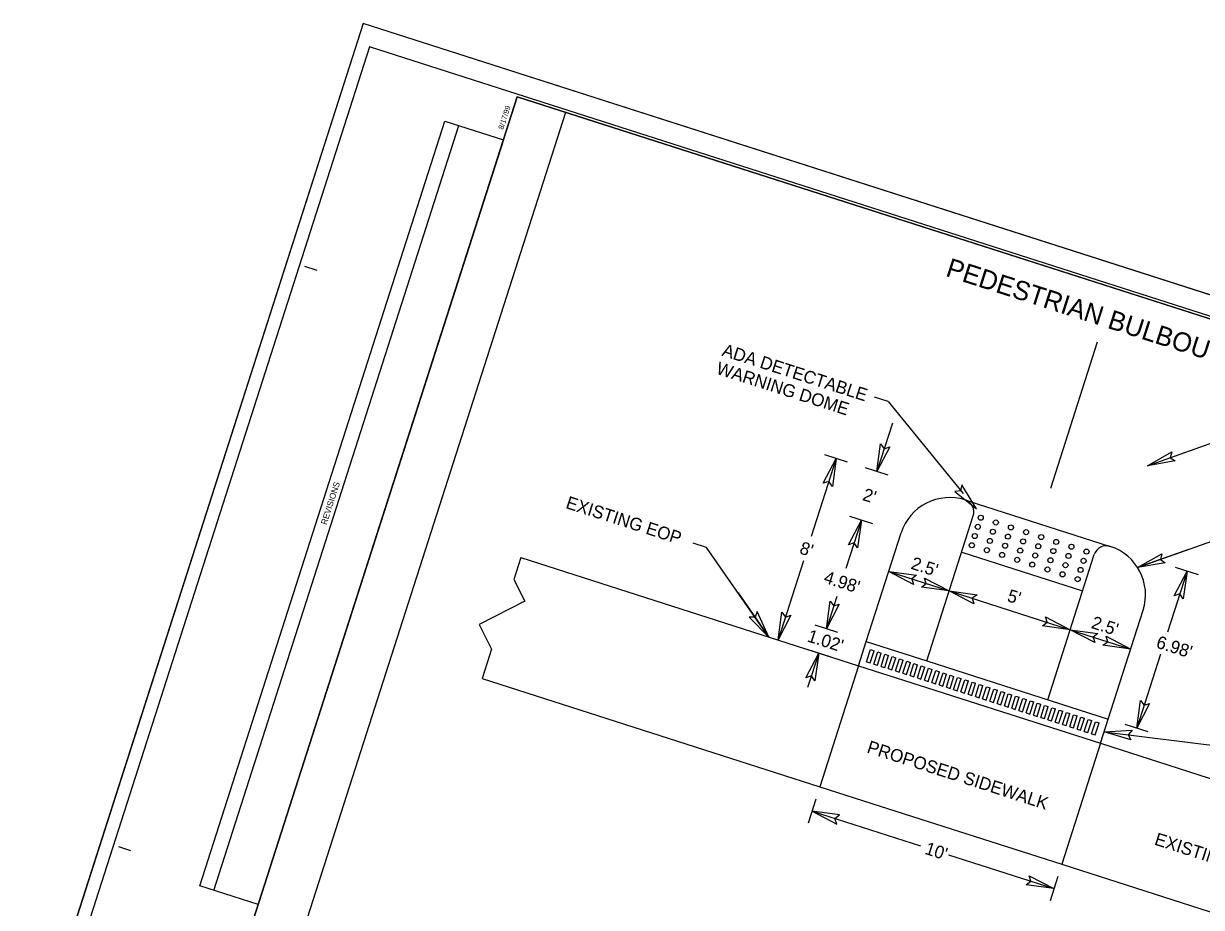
# Model space of a CAD drawing. Extents: x 928111 to 937215, y 684320 to 686530.
# Drawn here: x 933624.35 to 933670.73, y 684716.03 to 684750.83 of the extents above; entities that cross this region are included whole.
import ezdxf

# ---------------------------------------------------------------- set-up
doc = ezdxf.new("R2010")
doc.units = 0
for name, color, linetype in [('Default', 7, 'Continuous'), ('Exist Roads EOP', 7, 'Continuous'), ('Prop Conc 5in Monolithic Keyed In Island', 7, 'Continuous'), ('Prop Conc Curb 8in x 6in', 7, 'Continuous'), ('Prop Dimension', 7, 'Continuous'), ('Prop DSN Text', 7, 'Continuous'), ('Prop Mkg Solid White Crosswalks', 7, 'Continuous'), ('Prop Terminator CELL', 7, 'Continuous'), ('Sheet Block Revision CELL', 7, 'Continuous'), ('Sheet Clip Boundary CELL', 7, 'Continuous'), ('Sheet Cutting Line CELL', 7, 'Continuous'), ('Sheet Layout Plan Border', 7, 'Continuous'), ('Sheet Plan CELL', 7, 'Continuous'), ('Sheet Plan Layout CELL', 7, 'Continuous'), ('Sheet Plot Border Inside CELL', 7, 'Continuous'), ('Sheet Plot Border Outside CELL', 7, 'Continuous')]:
    doc.layers.add(name, color=color, linetype=linetype)

msp = doc.modelspace()

# ---------------------------------------------------------------- linework, layer by layer
at = {"layer": 'Default'}
for p, q in [((933658.389, 684735.948), (933661.338, 684732.328)), ((933670.213, 684730.121), (933668.213, 684729.41)), ((933652.482, 684728.417), (933653.696, 684726.676))]:
    msp.add_line(p, q, dxfattribs=at)
at = {"layer": 'Exist Roads EOP'}
for p, q in [((933643.933, 684729.806), (933643.654, 684728.936)), ((933643.933, 684729.806), (933657.227, 684725.544)), ((933643.654, 684728.936), (933644.089, 684728.092)), ((933644.089, 684728.092), (933642.286, 684727.164)), ((933642.286, 684727.164), (933642.779, 684726.205)), ((933642.779, 684726.205), (933642.407, 684725.044)), ((933642.407, 684725.044), (933655.701, 684720.783)), ((933666.75, 684722.492), (933680.951, 684717.94)), ((933665.223, 684717.731), (933679.425, 684713.179))]:
    msp.add_line(p, q, dxfattribs=at)
at = {"layer": 'Prop Conc 5in Monolithic Keyed In Island'}
for p, q in [((933659.913, 684725.734), (933661.744, 684731.447)), ((933657.532, 684726.497), (933658.906, 684730.782)), ((933664.674, 684724.207), (933666.506, 684729.921)), ((933667.055, 684723.444), (933668.428, 684727.73)), ((933657.227, 684725.544), (933657.532, 684726.497)), ((933657.541, 684725.706), (933657.694, 684726.182)), ((933657.684, 684725.66), (933657.837, 684726.137)), ((933657.694, 684726.182), (933657.837, 684726.137)), ((933657.827, 684725.615), (933657.979, 684726.091)), ((933657.97, 684725.569), (933658.122, 684726.045)), ((933657.979, 684726.091), (933658.122, 684726.045)), ((933658.113, 684725.523), (933658.265, 684725.999)), ((933658.255, 684725.477), (933658.408, 684725.953)), ((933658.265, 684725.999), (933658.408, 684725.953)), ((933658.398, 684725.432), (933658.551, 684725.908)), ((933658.551, 684725.908), (933658.694, 684725.862)), ((933657.227, 684725.544), (933655.701, 684720.783)), ((933657.227, 684725.544), (933659.607, 684724.781)), ((933657.541, 684725.706), (933657.684, 684725.66)), ((933657.827, 684725.615), (933657.97, 684725.569)), ((933658.113, 684725.523), (933658.255, 684725.477)), ((933658.541, 684725.386), (933658.694, 684725.862)), ((933658.684, 684725.34), (933658.836, 684725.816)), ((933658.827, 684725.294), (933658.979, 684725.77)), ((933658.836, 684725.816), (933658.979, 684725.77)), ((933658.97, 684725.248), (933659.122, 684725.724)), ((933659.112, 684725.203), (933659.265, 684725.679)), ((933659.122, 684725.724), (933659.265, 684725.679)), ((933659.255, 684725.157), (933659.408, 684725.633)), ((933659.398, 684725.111), (933659.551, 684725.587)), ((933659.408, 684725.633), (933659.551, 684725.587)), ((933659.541, 684725.065), (933659.694, 684725.541)), ((933659.684, 684725.019), (933659.836, 684725.496)), ((933659.694, 684725.541), (933659.836, 684725.496)), ((933659.827, 684724.974), (933659.979, 684725.45)), ((933659.979, 684725.45), (933660.122, 684725.404)), ((933658.398, 684725.432), (933658.541, 684725.386)), ((933658.684, 684725.34), (933658.827, 684725.294)), ((933658.97, 684725.248), (933659.112, 684725.203)), ((933659.255, 684725.157), (933659.398, 684725.111)), ((933659.541, 684725.065), (933659.684, 684725.019)), ((933659.827, 684724.974), (933659.969, 684724.928)), ((933659.969, 684724.928), (933660.122, 684725.404)), ((933660.112, 684724.882), (933660.265, 684725.358)), ((933660.255, 684724.836), (933660.408, 684725.312)), ((933660.265, 684725.358), (933660.408, 684725.312)), ((933660.398, 684724.79), (933660.551, 684725.267)), ((933660.541, 684724.745), (933660.693, 684725.221)), ((933660.551, 684725.267), (933660.693, 684725.221)), ((933660.684, 684724.699), (933660.836, 684725.175)), ((933660.826, 684724.653), (933660.979, 684725.129)), ((933660.836, 684725.175), (933660.979, 684725.129)), ((933660.969, 684724.607), (933661.122, 684725.083)), ((933661.112, 684724.562), (933661.265, 684725.038)), ((933661.122, 684725.083), (933661.265, 684725.038)), ((933661.255, 684724.516), (933661.408, 684724.992)), ((933661.408, 684724.992), (933661.55, 684724.946)), ((933659.607, 684724.781), (933666.75, 684722.492)), ((933660.112, 684724.882), (933660.255, 684724.836)), ((933660.398, 684724.79), (933660.541, 684724.745)), ((933660.684, 684724.699), (933660.826, 684724.653)), ((933660.969, 684724.607), (933661.112, 684724.562)), ((933661.255, 684724.516), (933661.398, 684724.47)), ((933661.398, 684724.47), (933661.55, 684724.946)), ((933661.541, 684724.424), (933661.693, 684724.9)), ((933661.684, 684724.378), (933661.836, 684724.855)), ((933661.693, 684724.9), (933661.836, 684724.855)), ((933661.826, 684724.333), (933661.979, 684724.809)), ((933661.969, 684724.287), (933662.122, 684724.763)), ((933661.979, 684724.809), (933662.122, 684724.763)), ((933662.112, 684724.241), (933662.265, 684724.717)), ((933662.255, 684724.195), (933662.408, 684724.671)), ((933662.265, 684724.717), (933662.408, 684724.671)), ((933662.398, 684724.149), (933662.55, 684724.626)), ((933662.541, 684724.104), (933662.693, 684724.58)), ((933662.55, 684724.626), (933662.693, 684724.58)), ((933662.683, 684724.058), (933662.836, 684724.534)), ((933662.836, 684724.534), (933662.979, 684724.488)), ((933661.541, 684724.424), (933661.684, 684724.378)), ((933661.826, 684724.333), (933661.969, 684724.287)), ((933662.112, 684724.241), (933662.255, 684724.195)), ((933662.398, 684724.149), (933662.541, 684724.104)), ((933662.683, 684724.058), (933662.826, 684724.012)), ((933662.826, 684724.012), (933662.979, 684724.488)), ((933662.969, 684723.966), (933663.122, 684724.442)), ((933663.112, 684723.921), (933663.265, 684724.397)), ((933663.122, 684724.442), (933663.265, 684724.397)), ((933663.255, 684723.875), (933663.407, 684724.351)), ((933663.398, 684723.829), (933663.55, 684724.305)), ((933663.407, 684724.351), (933663.55, 684724.305)), ((933663.54, 684723.783), (933663.693, 684724.259)), ((933663.683, 684723.737), (933663.836, 684724.214)), ((933663.693, 684724.259), (933663.836, 684724.214)), ((933663.826, 684723.692), (933663.979, 684724.168)), ((933663.969, 684723.646), (933664.122, 684724.122)), ((933663.979, 684724.168), (933664.122, 684724.122)), ((933664.112, 684723.6), (933664.264, 684724.076)), ((933664.264, 684724.076), (933664.407, 684724.03)), ((933662.969, 684723.966), (933663.112, 684723.921)), ((933663.255, 684723.875), (933663.398, 684723.829)), ((933663.54, 684723.783), (933663.683, 684723.737)), ((933663.826, 684723.692), (933663.969, 684723.646)), ((933664.112, 684723.6), (933664.255, 684723.554)), ((933664.255, 684723.554), (933664.407, 684724.03)), ((933664.398, 684723.508), (933664.55, 684723.985)), ((933664.54, 684723.463), (933664.693, 684723.939)), ((933664.55, 684723.985), (933664.693, 684723.939)), ((933664.683, 684723.417), (933664.836, 684723.893)), ((933664.826, 684723.371), (933664.979, 684723.847)), ((933664.836, 684723.893), (933664.979, 684723.847)), ((933664.969, 684723.325), (933665.122, 684723.801)), ((933665.112, 684723.28), (933665.264, 684723.756)), ((933665.122, 684723.801), (933665.264, 684723.756)), ((933665.255, 684723.234), (933665.407, 684723.71)), ((933665.397, 684723.188), (933665.55, 684723.664)), ((933665.407, 684723.71), (933665.55, 684723.664)), ((933665.54, 684723.142), (933665.693, 684723.618)), ((933665.693, 684723.618), (933665.836, 684723.573)), ((933664.398, 684723.508), (933664.54, 684723.463)), ((933664.683, 684723.417), (933664.826, 684723.371)), ((933664.969, 684723.325), (933665.112, 684723.28)), ((933665.255, 684723.234), (933665.397, 684723.188)), ((933665.54, 684723.142), (933665.683, 684723.096)), ((933665.683, 684723.096), (933665.836, 684723.573)), ((933665.826, 684723.051), (933665.979, 684723.527)), ((933665.969, 684723.005), (933666.121, 684723.481)), ((933665.979, 684723.527), (933666.121, 684723.481)), ((933666.112, 684722.959), (933666.264, 684723.435)), ((933666.254, 684722.913), (933666.407, 684723.389)), ((933666.264, 684723.435), (933666.407, 684723.389)), ((933666.397, 684722.867), (933666.55, 684723.344)), ((933666.54, 684722.822), (933666.693, 684723.298)), ((933666.55, 684723.344), (933666.693, 684723.298)), ((933666.75, 684722.492), (933667.055, 684723.444)), ((933665.826, 684723.051), (933665.969, 684723.005)), ((933666.112, 684722.959), (933666.254, 684722.913)), ((933666.397, 684722.867), (933666.54, 684722.822)), ((933666.75, 684722.492), (933665.223, 684717.731)), ((933655.701, 684720.783), (933658.081, 684720.02)), ((933658.081, 684720.02), (933665.223, 684717.731))]:
    msp.add_line(p, q, dxfattribs=at)
for centre, start, end in [((933660.81, 684730.171), 72.2273, 162.2273), ((933666.524, 684728.34), 342.2273, 72.2273)]:
    msp.add_arc(centre, 2, start, end, dxfattribs=at)
at = {"layer": 'Prop Conc Curb 8in x 6in'}
for p, q in [((933661.421, 684732.076), (933661.897, 684731.923)), ((933661.897, 684731.923), (933667.134, 684730.245)), ((933661.286, 684730.019), (933666.048, 684728.493)), ((933657.532, 684726.497), (933659.913, 684725.734)), ((933659.913, 684725.734), (933667.055, 684723.444))]:
    msp.add_line(p, q, dxfattribs=at)
for centre in [(933662.034, 684731.377), (933661.918, 684731.015), (933662.63, 684731.186), (933663.225, 684730.995), (933661.802, 684730.652), (933662.397, 684730.462), (933662.514, 684730.824), (933663.109, 684730.633), (933663.704, 684730.442), (933663.82, 684730.805), (933664.415, 684730.614), (933661.686, 684730.29), (933662.281, 684730.099), (933662.993, 684730.271), (933663.588, 684730.08), (933664.299, 684730.252), (933664.894, 684730.061), (933665.01, 684730.423), (933665.606, 684730.232), (933666.201, 684730.041), (933662.876, 684729.909), (933663.472, 684729.718), (933664.067, 684729.527), (933664.183, 684729.889), (933664.778, 684729.699), (933665.373, 684729.508), (933665.489, 684729.87), (933666.085, 684729.679), (933664.662, 684729.336), (933665.257, 684729.146), (933665.968, 684729.317), (933665.852, 684728.955)]:
    msp.add_circle(centre, 0.1, dxfattribs=at)
for centre, start, end in [((933661.268, 684731.6), 342.2273, 72.2273), ((933666.982, 684729.768), 72.2273, 162.2273)]:
    msp.add_arc(centre, 0.5, start, end, dxfattribs=at)
at = {"layer": 'Prop Dimension'}
for p, q in [((933658.389, 684735.948), (933657.859, 684736.117)), ((933658.557, 684735.094), (933657.946, 684733.19)), ((933668.606, 684733.422), (933672.653, 684734.861)), ((933656.796, 684733.558), (933655.896, 684733.847)), ((933656.346, 684733.703), (933655.361, 684730.63)), ((933658.396, 684733.045), (933657.496, 684733.334)), ((933657.336, 684731.285), (933656.725, 684729.381)), ((933657.786, 684731.141), (933656.886, 684731.429)), ((933668.213, 684729.41), (933672.26, 684730.849)), ((933651.239, 684730.199), (933650.71, 684730.369)), ((933653.696, 684726.676), (933651.239, 684730.199)), ((933655.056, 684729.678), (933654.057, 684726.561)), ((933658.417, 684729.256), (933660.797, 684728.493)), ((933670.159, 684729.275), (933669.388, 684726.87)), ((933670.608, 684729.131), (933669.709, 684729.419)), ((933656.372, 684728.278), (933655.962, 684727)), ((933660.797, 684728.493), (933665.559, 684726.967)), ((933656.412, 684726.856), (933655.512, 684727.144)), ((933665.559, 684726.967), (933667.939, 684726.204)), ((933656.107, 684725.903), (933655.207, 684726.192)), ((933655.657, 684726.048), (933655.221, 684724.689)), ((933669.111, 684726.008), (933668.175, 684723.085)), ((933668.624, 684722.941), (933667.725, 684723.23)), ((933666.895, 684722.947), (933672.353, 684722.265)), ((933655.545, 684720.298), (933655.24, 684719.346)), ((933655.393, 684719.822), (933659.667, 684718.452)), ((933660.763, 684718.101), (933664.915, 684716.77)), ((933665.068, 684717.246), (933664.763, 684716.294))]:
    msp.add_line(p, q, dxfattribs=at)
at = {"layer": 'Prop Mkg Solid White Crosswalks'}
msp.add_line((933664.79, 684732.544), (933666.633, 684738.296), dxfattribs=at)
msp.add_lwpolyline([(933669.686, 684733.609), (933668.606, 684733.422), (933669.565, 684733.967), (933669.499, 684733.74)], close=True, dxfattribs=at)
at = {"layer": 'Prop Terminator CELL'}
for points in [[(933658.453, 684734.161), (933657.946, 684733.19), (933658.095, 684734.282), (933658.236, 684734.092)], [(933655.839, 684732.731), (933656.346, 684733.703), (933656.198, 684732.61), (933656.057, 684732.8)], [(933661.017, 684732.412), (933661.869, 684731.722), (933661.298, 684732.666), (933661.244, 684732.435)], [(933656.829, 684730.313), (933657.336, 684731.285), (933657.187, 684730.192), (933657.047, 684730.382)], [(933669.293, 684729.597), (933668.213, 684729.41), (933669.172, 684729.955), (933669.107, 684729.728)], [(933659.388, 684728.749), (933658.417, 684729.256), (933659.509, 684729.108), (933659.319, 684728.967)], [(933669.652, 684728.303), (933670.159, 684729.275), (933670.01, 684728.182), (933669.869, 684728.372)], [(933659.826, 684729), (933660.797, 684728.493), (933659.704, 684728.642), (933659.894, 684728.782)], [(933661.769, 684727.986), (933660.797, 684728.493), (933661.89, 684728.344), (933661.7, 684728.204)], [(933656.469, 684727.972), (933655.962, 684727), (933656.111, 684728.093), (933656.252, 684727.903)], [(933652.925, 684727.456), (933653.696, 684726.676), (933653.232, 684727.677), (933653.153, 684727.454)], [(933654.564, 684727.532), (933654.057, 684726.561), (933654.206, 684727.653), (933654.346, 684727.463)], [(933664.587, 684727.474), (933665.559, 684726.967), (933664.466, 684727.116), (933664.656, 684727.256)], [(933666.53, 684726.46), (933665.559, 684726.967), (933666.651, 684726.818), (933666.461, 684726.678)], [(933666.968, 684726.711), (933667.939, 684726.204), (933666.847, 684726.352), (933667.037, 684726.493)], [(933655.15, 684725.076), (933655.657, 684726.048), (933655.508, 684724.955), (933655.368, 684725.145)], [(933668.681, 684724.057), (933668.175, 684723.085), (933668.323, 684724.178), (933668.464, 684723.988)], [(933667.944, 684722.629), (933666.895, 684722.947), (933667.997, 684723.003), (933667.836, 684722.83)], [(933656.478, 684719.67), (933655.393, 684719.822), (933656.368, 684719.308), (933656.295, 684719.533)], [(933663.944, 684717.276), (933664.915, 684716.77), (933663.823, 684716.918), (933664.013, 684717.059)]]:
    msp.add_lwpolyline(points, close=True, dxfattribs=at)
at = {"layer": 'Sheet Block Revision CELL'}
msp.add_line((933631.842, 684716.701), (933641.495, 684746.817), dxfattribs=at)
msp.add_lwpolyline([(933631.288, 684716.877), (933640.941, 684746.994), (933643.248, 684746.256), (933633.594, 684716.139)], close=True, dxfattribs=at)
at = {"layer": 'Sheet Clip Boundary CELL'}
msp.add_lwpolyline([(933632.873, 684707.339), (933686.201, 684690.246), (933696.439, 684722.185), (933689.23, 684724.496), (933691.812, 684732.552), (933645.693, 684747.335)], close=True, dxfattribs=at)
at = {"layer": 'Sheet Cutting Line CELL'}
for p, q in [((933637.722, 684750.835), (933624.352, 684709.125)), ((933701.848, 684730.28), (933637.722, 684750.835))]:
    msp.add_line(p, q, dxfattribs=at)
at = {"layer": 'Sheet Layout Plan Border'}
msp.add_lwpolyline([(933632.873, 684707.339), (933686.201, 684690.246), (933696.439, 684722.185), (933689.23, 684724.496), (933691.812, 684732.552), (933645.693, 684747.335)], close=True, dxfattribs=at)
at = {"layer": 'Sheet Plan CELL'}
for p, q in [((933643.789, 684747.945), (933643.789, 684747.945)), ((933635.415, 684741.282), (933635.892, 684741.13)), ((933628.091, 684718.428), (933628.567, 684718.275))]:
    msp.add_line(p, q, dxfattribs=at)
for points in [[(933700.927, 684729.63), (933643.789, 684747.945), (933630.969, 684707.95), (933688.106, 684689.635)], [(933630.969, 684707.95), (933643.787, 684747.945), (933693.306, 684732.074), (933691.474, 684726.358), (933699.093, 684723.915), (933688.106, 684689.635)]]:
    msp.add_lwpolyline(points, close=True, dxfattribs=at)
at = {"layer": 'Sheet Plan Layout CELL'}
msp.add_lwpolyline([(933643.787, 684747.945), (933630.969, 684707.95), (933688.105, 684689.635), (933698.343, 684721.575), (933689.23, 684724.496), (933691.812, 684732.552)], close=True, dxfattribs=at)
at = {"layer": 'Sheet Plot Border Inside CELL'}
msp.add_lwpolyline([(933625.091, 684709.728), (933688.551, 684689.388), (933701.432, 684729.573), (933637.973, 684749.914)], close=True, dxfattribs=at)
at = {"layer": 'Sheet Plot Border Outside CELL'}
msp.add_lwpolyline([(933624.352, 684709.125), (933688.478, 684688.57), (933701.848, 684730.28), (933637.722, 684750.835)], close=True, dxfattribs=at)

# ---------------------------------------------------------------- texts
at = {"layer": 'Prop DSN Text'}
for s, height, p in [('PEDESTRIAN BULBOUT DETAIL ', 0.75, (933660.619, 684740.9)), ('ADA DETECTABLE', 0.5, (933651.817, 684737.766)), ('WARNING DOME', 0.5, (933651.588, 684737.052)), ("2'", 0.5, (933657.348, 684732.079)), ('EXISTING EOP', 0.5, (933645.665, 684731.761)), ("8'", 0.5, (933654.868, 684729.976)), ("2.5'", 0.5, (933659.253, 684729.372)), ("4.98'", 0.5, (933655.822, 684728.826)), ("5'", 0.5, (933663.043, 684728.097)), ("2.5'", 0.5, (933666.354, 684727.039)), ("1.02'", 0.5, (933655.171, 684726.513)), ("6.98'", 0.5, (933668.907, 684726.27)), ('PROPOSED SIDEWALK ', 0.5, (933657.522, 684722.138)), ('EXISTING SIDEWALK ', 0.5, (933668.841, 684718.51)), ("10'", 0.5, (933659.801, 684718.146))]:
    msp.add_text(s, height=height, rotation=342.2273, dxfattribs=at).set_placement(p)
at = {"layer": 'Sheet Block Revision CELL'}
msp.add_text('REVISIONS', height=0.24, rotation=72.2273, dxfattribs=at).set_placement((933636.281, 684731.078))
at = {"layer": 'Sheet Plan CELL'}
msp.add_text('8/17/99', height=0.21, rotation=72.2273, dxfattribs=at).set_placement((933643.236, 684746.643))

doc.saveas('drawing.dxf')
